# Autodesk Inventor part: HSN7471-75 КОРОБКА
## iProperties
Created: 2011-02
Part Number: HSN7471-75 КОРОБКА
Document SubType Name: Modeling
Designer: Чернышев Юрий
Mass: 9826.53 g
Surface Area: 3294.27 cm^2
Volume: 9826.53 cm^3
Density: 1 g/cm^3
Author: Чернышев Юрий
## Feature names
1. ExtrusionBlind1
2. Fillet1
3. Fillet2
